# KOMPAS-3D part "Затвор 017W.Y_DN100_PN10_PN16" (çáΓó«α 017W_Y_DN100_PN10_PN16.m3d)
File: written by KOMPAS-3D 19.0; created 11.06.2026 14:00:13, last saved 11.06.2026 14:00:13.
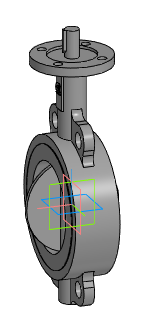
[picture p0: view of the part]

Document properties: Автор: Евгений; Полное имя файла: Z:\3.Личные\kachalov\001_3d для проектировщиков\x.x Тип 017W.Y(S) Затвор дисковый поворотный межфланцевый\_stp_Затвор 017W.Y_DN50-DN350\Затвор 017W_Y_DN100_PN10_PN16.m3d

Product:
- Part/product: Затвор 017W.Y_DN100_PN10_PN16

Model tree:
1. Операция без истории:1  (labels: Затвор 017W.Y_DN100_PN10_PN16)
